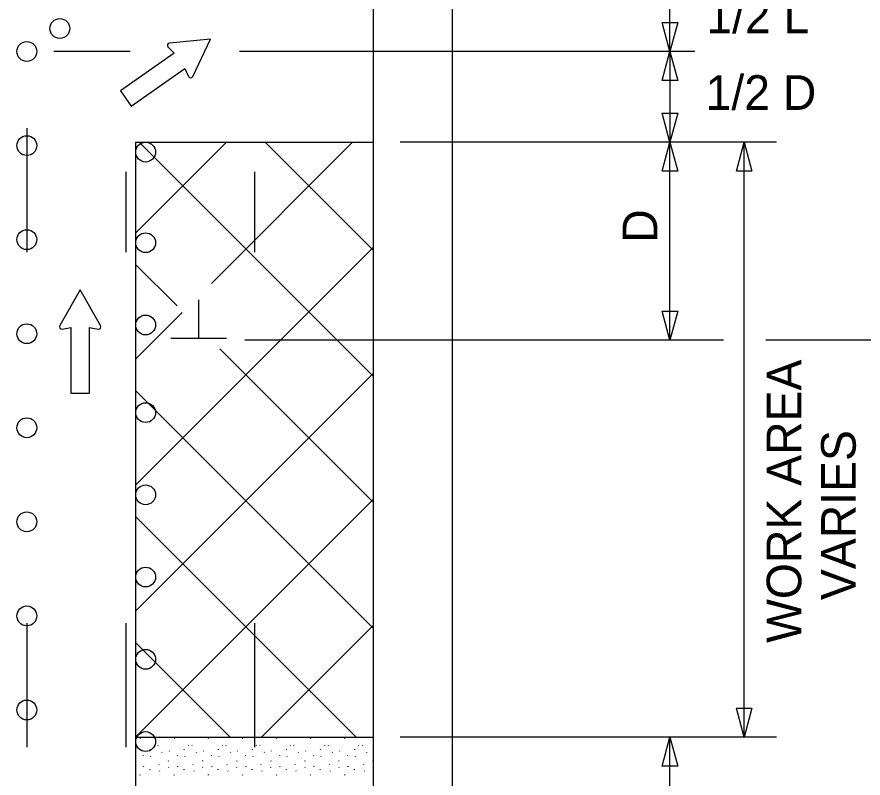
# Model space of a CAD drawing. Extents: x 16525 to 18478, y 5730 to 6927.
# Drawn here: x 17075.6 to 17246.6, y 6523 to 6676.7 of the extents above; entities that cross this region are included whole.
import ezdxf

# ---------------------------------------------------------------- set-up
doc = ezdxf.new("R2010")
doc.units = 0
for name, color, linetype in [('ALI_LEGAL_EX', 7, 'Continuous'), ('MT_SCRATCH_LEVEL_A', 7, 'Continuous'), ('MT_SCRATCH_LEVEL_E', 7, 'Continuous'), ('PAVT_EDGE_EX', 7, 'Continuous'), ('TRAFFIC_SIGNS_PR', 7, 'Continuous'), ('TYPICAL_TEXT_DIMEN_PR', 7, 'Continuous')]:
    doc.layers.add(name, color=color, linetype=linetype)

msp = doc.modelspace()

# ---------------------------------------------------------------- linework, layer by layer
at = {"layer": 'ALI_LEGAL_EX'}
for points in [[(17077.59, 6654.22), (17077.59, 6629.22)], [(17097.59, 6645.4), (17097.59, 6629.22)], [(17123.59, 6645.4), (17123.59, 6629.22)], [(17077.59, 6554.22), (17077.59, 6529.22)], [(17097.59, 6554.22), (17097.59, 6529.22)], [(17123.59, 6554.22), (17123.59, 6529.22)]]:
    msp.add_lwpolyline(points, dxfattribs=at)
at = {"layer": 'MT_SCRATCH_LEVEL_A'}
for p, q in [((17099.59, 6651.4), (17147.59, 6651.4)), ((17099.59, 6633.05), (17117.94, 6651.4)), ((17147.59, 6604.14), (17100.33, 6651.4)), ((17114.89, 6622.89), (17143.4, 6651.4)), ((17147.59, 6629.6), (17125.78, 6651.4)), ((17099.59, 6582.14), (17147.59, 6630.14)), ((17107.95, 6618.33), (17099.59, 6626.69)), ((17099.59, 6607.59), (17109.02, 6617.02)), ((17147.59, 6578.69), (17116.62, 6609.66)), ((17099.59, 6556.68), (17147.59, 6604.68)), ((17147.59, 6553.23), (17099.59, 6601.23)), ((17099.59, 6531.23), (17147.59, 6579.23)), ((17144.14, 6531.23), (17099.59, 6575.78)), ((17125.04, 6531.23), (17147.59, 6553.77)), ((17118.68, 6531.23), (17099.59, 6550.32)), ((17099.59, 6531.23), (17147.59, 6531.23)), ((17099.59, 6531.23), (17099.59, 6531.23)), ((17100.51, 6530.87), (17100.57, 6530.99)), ((17107.4, 6530.87), (17107.46, 6530.99)), ((17114.29, 6530.87), (17114.34, 6530.99)), ((17121.18, 6530.87), (17121.23, 6530.99)), ((17128.06, 6530.87), (17128.12, 6530.99)), ((17134.95, 6530.87), (17135.01, 6530.99)), ((17141.84, 6530.87), (17141.89, 6530.99)), ((17102.53, 6528.67), (17102.59, 6528.79)), ((17103.3, 6529.63), (17103.35, 6529.55)), ((17104.04, 6529.6), (17104.09, 6529.53)), ((17109.42, 6528.67), (17109.47, 6528.79)), ((17110.19, 6529.63), (17110.24, 6529.55)), ((17110.92, 6529.6), (17110.98, 6529.53)), ((17116.31, 6528.67), (17116.36, 6528.79)), ((17117.07, 6529.63), (17117.13, 6529.55)), ((17117.81, 6529.6), (17117.86, 6529.53)), ((17123.2, 6528.67), (17123.25, 6528.79)), ((17123.96, 6529.63), (17124.01, 6529.55)), ((17124.7, 6529.6), (17124.75, 6529.53)), ((17130.08, 6528.67), (17130.14, 6528.79)), ((17130.85, 6529.63), (17130.9, 6529.55)), ((17131.59, 6529.6), (17131.64, 6529.53)), ((17136.97, 6528.67), (17137.02, 6528.79)), ((17137.74, 6529.63), (17137.79, 6529.55)), ((17138.47, 6529.6), (17138.53, 6529.53)), ((17143.86, 6528.67), (17143.91, 6528.79)), ((17144.62, 6529.63), (17144.68, 6529.55)), ((17145.36, 6529.6), (17145.41, 6529.53)), ((17101.08, 6527.55), (17101.14, 6527.47)), ((17102.62, 6527.41), (17102.67, 6527.33)), ((17104.9, 6528.22), (17104.96, 6528.15)), ((17106.35, 6528.38), (17106.41, 6528.49)), ((17107.97, 6527.55), (17108.02, 6527.47)), ((17109.5, 6527.41), (17109.55, 6527.33)), ((17111.79, 6528.22), (17111.84, 6528.15)), ((17113.24, 6528.38), (17113.29, 6528.49)), ((17114.86, 6527.55), (17114.91, 6527.47)), ((17116.39, 6527.41), (17116.44, 6527.33)), ((17118.68, 6528.22), (17118.73, 6528.15)), ((17120.13, 6528.38), (17120.18, 6528.49)), ((17121.75, 6527.55), (17121.8, 6527.47)), ((17123.28, 6527.41), (17123.33, 6527.33)), ((17125.57, 6528.22), (17125.62, 6528.15)), ((17127.02, 6528.38), (17127.07, 6528.49)), ((17128.64, 6527.55), (17128.69, 6527.47)), ((17130.17, 6527.41), (17130.22, 6527.33)), ((17132.46, 6528.22), (17132.51, 6528.15)), ((17133.9, 6528.38), (17133.96, 6528.49)), ((17135.52, 6527.55), (17135.57, 6527.47)), ((17137.05, 6527.41), (17137.1, 6527.33)), ((17139.34, 6528.22), (17139.39, 6528.15)), ((17140.79, 6528.38), (17140.84, 6528.49)), ((17142.41, 6527.55), (17142.46, 6527.47)), ((17143.94, 6527.41), (17143.99, 6527.33)), ((17146.23, 6528.22), (17146.28, 6528.15)), ((17101.13, 6525.34), (17101.19, 6525.26)), ((17104.26, 6525.62), (17104.31, 6525.73)), ((17106.18, 6526.49), (17106.23, 6526.41)), ((17106.22, 6525.09), (17106.28, 6525.2)), ((17108.02, 6525.34), (17108.07, 6525.26)), ((17111.14, 6525.62), (17111.2, 6525.73)), ((17113.07, 6526.49), (17113.12, 6526.41)), ((17113.11, 6525.09), (17113.16, 6525.2)), ((17114.91, 6525.34), (17114.96, 6525.26)), ((17118.03, 6525.62), (17118.08, 6525.73)), ((17119.96, 6526.49), (17120.01, 6526.41)), ((17120, 6525.09), (17120.05, 6525.2)), ((17121.8, 6525.34), (17121.85, 6525.26)), ((17124.92, 6525.62), (17124.97, 6525.73)), ((17126.85, 6526.49), (17126.9, 6526.41)), ((17126.89, 6525.09), (17126.94, 6525.2)), ((17128.68, 6525.34), (17128.74, 6525.26)), ((17131.81, 6525.62), (17131.86, 6525.73)), ((17133.73, 6526.49), (17133.78, 6526.41)), ((17133.78, 6525.09), (17133.83, 6525.2)), ((17135.57, 6525.34), (17135.62, 6525.26)), ((17138.69, 6525.62), (17138.75, 6525.73)), ((17140.62, 6526.49), (17140.67, 6526.41)), ((17140.66, 6525.09), (17140.71, 6525.2)), ((17142.46, 6525.34), (17142.51, 6525.26)), ((17145.58, 6525.62), (17145.63, 6525.73)), ((17147.51, 6526.49), (17147.56, 6526.41)), ((17147.55, 6525.09), (17147.6, 6525.2)), ((17100.51, 6523.58), (17100.57, 6523.7)), ((17102.42, 6524.76), (17102.43, 6524.64)), ((17104.44, 6524.42), (17104.5, 6524.34)), ((17107.4, 6523.58), (17107.46, 6523.7)), ((17109.3, 6524.76), (17109.32, 6524.64)), ((17111.33, 6524.42), (17111.38, 6524.34)), ((17114.29, 6523.58), (17114.34, 6523.7)), ((17116.19, 6524.76), (17116.2, 6524.64)), ((17118.22, 6524.42), (17118.27, 6524.34)), ((17121.18, 6523.58), (17121.23, 6523.7)), ((17123.08, 6524.76), (17123.09, 6524.64)), ((17125.11, 6524.42), (17125.16, 6524.34)), ((17128.06, 6523.58), (17128.12, 6523.7)), ((17129.97, 6524.76), (17129.98, 6524.64)), ((17131.99, 6524.42), (17132.05, 6524.34)), ((17134.95, 6523.58), (17135.01, 6523.7)), ((17136.85, 6524.76), (17136.87, 6524.64)), ((17138.88, 6524.42), (17138.93, 6524.34)), ((17141.84, 6523.58), (17141.89, 6523.7)), ((17143.74, 6524.76), (17143.75, 6524.64)), ((17145.77, 6524.42), (17145.82, 6524.34))]:
    msp.add_line(p, q, dxfattribs=at)
at = {"layer": 'MT_SCRATCH_LEVEL_E'}
for p, q in [((17106.11, 6670.64), (17107.39, 6669.36)), ((17106.11, 6670.64), (17107.39, 6669.36)), ((17114.69, 6672.2), (17106.4, 6671.43)), ((17114.69, 6672.2), (17106.4, 6671.43)), ((17111.13, 6664.66), (17114.69, 6672.2)), ((17111.13, 6664.66), (17114.69, 6672.2)), ((17107.39, 6669.36), (17096.52, 6661.77)), ((17107.39, 6669.36), (17096.52, 6661.77)), ((17098.66, 6658.7), (17109.53, 6666.3)), ((17098.66, 6658.7), (17109.53, 6666.3)), ((17109.53, 6666.3), (17110.29, 6664.66)), ((17109.53, 6666.3), (17110.29, 6664.66)), ((17096.52, 6661.77), (17098.66, 6658.7)), ((17096.52, 6661.77), (17098.66, 6658.7)), ((17088.36, 6621.59), (17084.25, 6614.35)), ((17088.36, 6621.59), (17084.25, 6614.35)), ((17092.5, 6614.35), (17088.36, 6621.59)), ((17092.5, 6614.35), (17088.36, 6621.59)), ((17084.73, 6613.66), (17086.51, 6613.98)), ((17084.73, 6613.66), (17086.51, 6613.98)), ((17086.51, 6613.98), (17086.51, 6600.72)), ((17086.51, 6613.98), (17086.51, 6600.72)), ((17090.25, 6600.72), (17090.25, 6613.98)), ((17090.25, 6613.98), (17092.03, 6613.66)), ((17090.25, 6600.72), (17090.25, 6613.98)), ((17090.25, 6613.98), (17092.03, 6613.66)), ((17086.51, 6600.72), (17090.25, 6600.72)), ((17086.51, 6600.72), (17090.25, 6600.72))]:
    msp.add_line(p, q, dxfattribs=at)
for centre, start, end in [((17106.45, 6670.96), 95.3561, 224.895), ((17106.45, 6670.96), 95.3561, 224.895), ((17110.71, 6664.86), 204.9674, 334.7043), ((17110.71, 6664.86), 204.9674, 334.7043), ((17084.65, 6614.12), 150.4248, 279.9638), ((17084.65, 6614.12), 150.4248, 279.9638), ((17092.09, 6614.12), 260.0362, 29.7731), ((17092.09, 6614.12), 260.0362, 29.7731)]:
    msp.add_arc(centre, 0.463, start, end, dxfattribs=at)
at = {"layer": 'PAVT_EDGE_EX'}
for p, q in [((17147.59, 6917.57), (17147.59, 6063.18)), ((17163.59, 6917.57), (17163.59, 6063.18)), ((17099.59, 6651.4), (17099.59, 6499.17))]:
    msp.add_line(p, q, dxfattribs=at)
at = {"layer": 'TRAFFIC_SIGNS_PR'}
for centre in [(17084.26, 6674.37), (17077.59, 6669.72), (17077.59, 6650.72), (17101.61, 6649.4), (17077.59, 6631.72), (17101.61, 6631.09), (17101.61, 6614.48), (17077.59, 6612.72), (17101.61, 6596.79), (17077.59, 6593.72), (17101.61, 6580.18), (17077.59, 6574.72), (17101.61, 6563.56), (17077.59, 6555.72), (17101.61, 6546.95), (17077.59, 6536.72), (17101.61, 6530.34)]:
    msp.add_circle(centre, 2, dxfattribs=at)
at = {"layer": 'TYPICAL_TEXT_DIMEN_PR'}
for p, q in [((17207.59, 6669.72), (17207.59, 6685.69)), ((17207.59, 6669.72), (17206.02, 6675.58)), ((17206.02, 6675.58), (17207.59, 6675.58)), ((17207.59, 6675.58), (17209.16, 6675.58)), ((17209.16, 6675.58), (17207.59, 6669.72)), ((17098.49, 6669.72), (17083.03, 6669.72)), ((17212.59, 6669.72), (17120.57, 6669.72)), ((17206.02, 6663.86), (17207.59, 6669.72)), ((17207.59, 6669.72), (17209.16, 6663.86)), ((17207.59, 6669.72), (17207.59, 6651.4)), ((17207.59, 6663.86), (17206.02, 6663.86)), ((17209.16, 6663.86), (17207.59, 6663.86)), ((17207.59, 6651.4), (17206.02, 6657.26)), ((17206.02, 6657.26), (17207.59, 6657.26)), ((17207.59, 6657.26), (17209.16, 6657.26)), ((17209.16, 6657.26), (17207.59, 6651.4)), ((17229.13, 6651.4), (17153.09, 6651.4)), ((17206.02, 6645.54), (17207.59, 6651.4)), ((17207.59, 6611.4), (17207.59, 6651.4)), ((17207.59, 6651.4), (17209.16, 6645.54)), ((17221.02, 6645.54), (17222.59, 6651.4)), ((17222.59, 6531.23), (17222.59, 6651.4)), ((17222.59, 6651.4), (17224.16, 6645.54)), ((17207.59, 6645.54), (17206.02, 6645.54)), ((17209.16, 6645.54), (17207.59, 6645.54)), ((17222.59, 6645.54), (17221.02, 6645.54)), ((17224.16, 6645.54), (17222.59, 6645.54)), ((17112.33, 6611.74), (17112.33, 6619.53)), ((17207.59, 6611.4), (17206.02, 6617.26)), ((17206.02, 6617.26), (17207.59, 6617.26)), ((17207.59, 6617.26), (17209.16, 6617.26)), ((17209.16, 6617.26), (17207.59, 6611.4)), ((17117.95, 6611.74), (17106.7, 6611.74)), ((17218.42, 6611.4), (17121.69, 6611.4)), ((17252.79, 6611.4), (17226.95, 6611.4)), ((17222.59, 6531.23), (17221.02, 6537.09)), ((17221.02, 6537.09), (17222.59, 6537.09)), ((17222.59, 6537.09), (17224.16, 6537.09)), ((17224.16, 6537.09), (17222.59, 6531.23)), ((17229.13, 6531.23), (17153.09, 6531.23)), ((17206.02, 6525.36), (17207.59, 6531.23)), ((17207.59, 6499.17), (17207.59, 6531.23)), ((17207.59, 6531.23), (17209.16, 6525.36)), ((17207.59, 6525.36), (17206.02, 6525.36)), ((17209.16, 6525.36), (17207.59, 6525.36))]:
    msp.add_line(p, q, dxfattribs=at)

# ---------------------------------------------------------------- texts
for s, p in [('1/2 L', (17214.94, 6673.41)), ('1/2 D', (17214.8, 6657.93))]:
    msp.add_text(s, height=7, dxfattribs=at).set_placement(p)
for s, p in [('D', (17205.03, 6631.09)), ('WORK AREA', (17234.14, 6550.27)), ('VARIES', (17245.14, 6558.91))]:
    msp.add_text(s, height=7, rotation=90, dxfattribs=at).set_placement(p)

doc.saveas('drawing.dxf')
